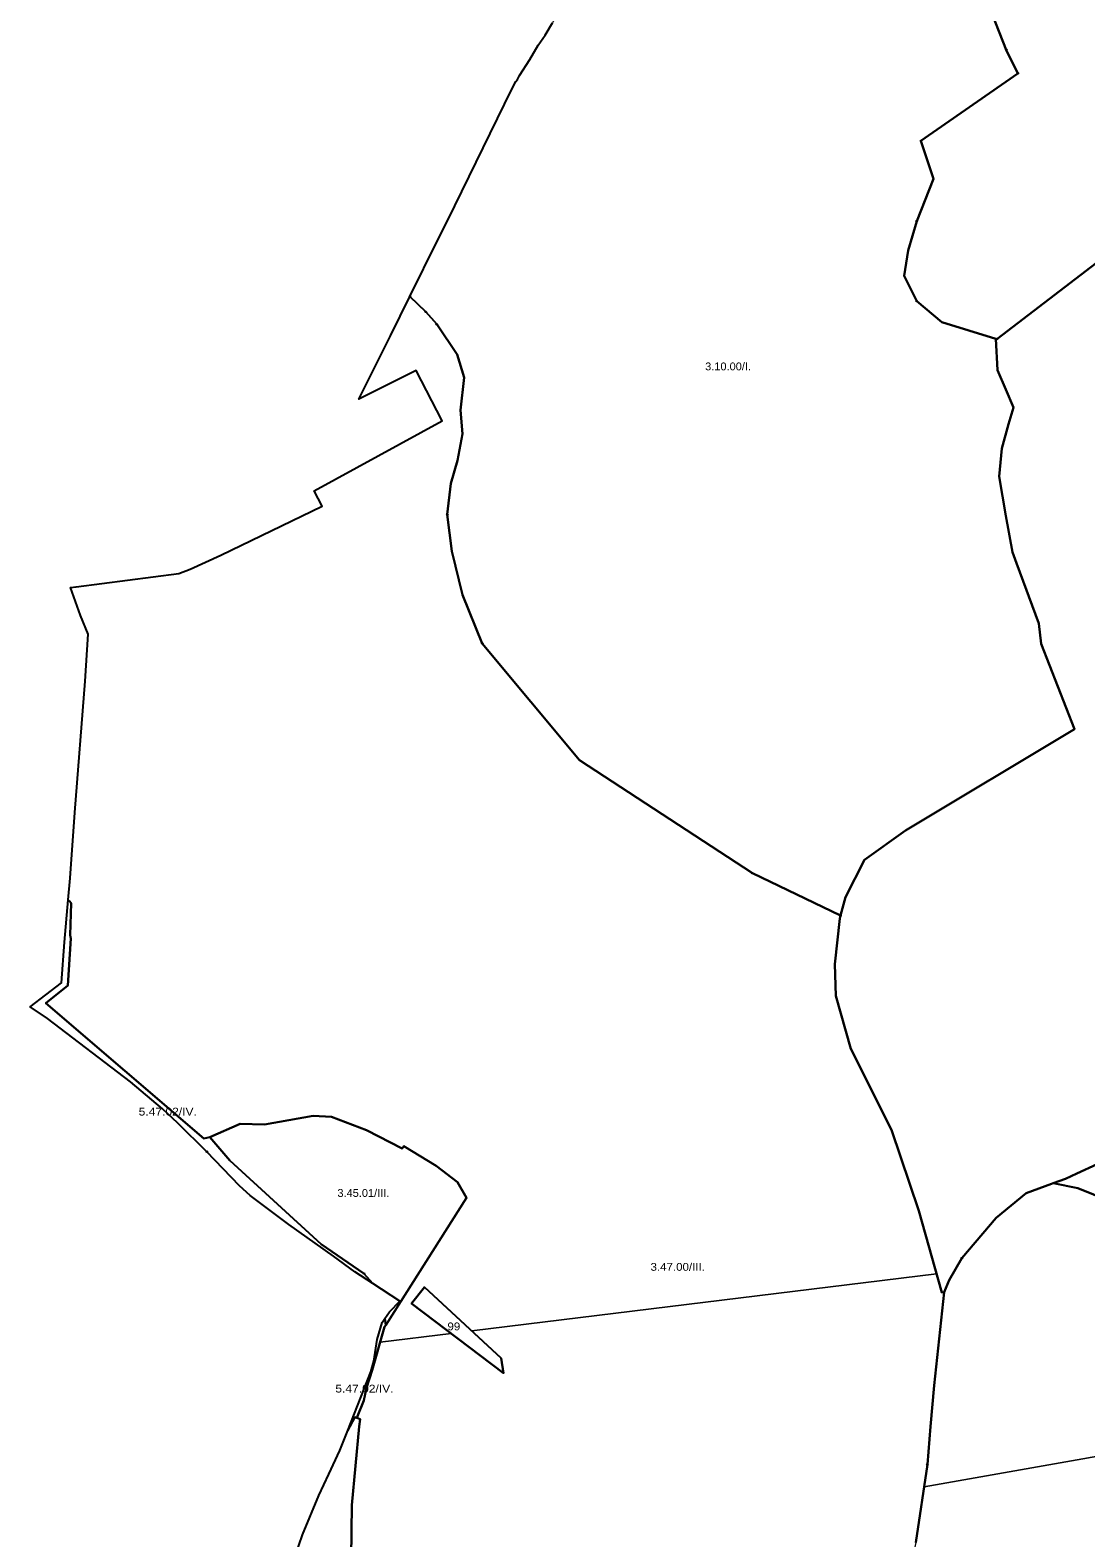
# Model space of a CAD drawing. Extents: x -650455 to -642254, y -1075222 to -1066610.
# Drawn here: x -649036 to -647687, y -1073142 to -1071216 of the extents above; entities that cross this region are included whole.
import ezdxf
from ezdxf.enums import TextEntityAlignment as Align

# ---------------------------------------------------------------- set-up
doc = ezdxf.new("R2010")
doc.units = 0
doc.header["$LTSCALE"] = 4
doc.header["$PDMODE"] = 32
doc.header["$PDSIZE"] = 2
for name, color, linetype, lineweight in [('1', 7, 'Continuous', 25), ('11', 7, 'Continuous', 13), ('12', 7, 'Continuous', 13), ('13', 7, 'Continuous', 13), ('14', 7, 'Continuous', 13)]:
    doc.layers.add(name, color=color, linetype=linetype, lineweight=lineweight)
doc.layers.add('2', color=7, linetype='Continuous')

msp = doc.modelspace()

# ---------------------------------------------------------------- linework, layer by layer
at = {"layer": '1'}
for points in [[(-647994, -1072324), (-648000.504, -1072347.414), (-648113.117, -1072293.193), (-648334.004, -1072148.767), (-648458.304, -1071999.711), (-648483.733, -1071937.503), (-648497.128, -1071881.651), (-648503.031, -1071835.108), (-648498.263, -1071795.376), (-648489.863, -1071765.861), (-648483.733, -1071731.805), (-648486, -1071701.501), (-648481.5, -1071660), (-648490.5, -1071630.501), (-648516.5, -1071592), (-648530.5, -1071576.001), (-648550.69, -1071556.284), (-648515.528, -1071484.719), (-648502.316, -1071458.869), (-648421.035, -1071292.285), (-648415.434, -1071281.946), (-648413.28, -1071279.36), (-648410.551, -1071274.192), (-648397.483, -1071253.511), (-648386.713, -1071235.418), (-648378.097, -1071222.492), (-648368.619, -1071206.983)], [(-647806.937, -1071195.687), (-647788.736, -1071241.189), (-647773.924, -1071271.486), (-647897.806, -1071357.665), (-647881.648, -1071406.14), (-647903.192, -1071460.002), (-647913.965, -1071497.705), (-647919.351, -1071530.022), (-647903.192, -1071562.339), (-647870.875, -1071589.27), (-647801.949, -1071610.478), (-647799.782, -1071650.366), (-647789.455, -1071675.321), (-647779.56, -1071698.124), (-647786.013, -1071719.637), (-647794.619, -1071750.616), (-647797.63, -1071786.328), (-647789.455, -1071836.453), (-647780.85, -1071882.921), (-647775.687, -1071897.12), (-647747.29, -1071974.351), (-647744.278, -1072000.167), (-647701.628, -1072109.378), (-647917.5, -1072238.5), (-647970, -1072276), (-647994, -1072324)], [(-647412.981, -1071489.088), (-647446.149, -1071408.082), (-647470.706, -1071328.032), (-647494.813, -1071270.777), (-647498.258, -1071279.39), (-647499.23, -1071276.872), (-647515.389, -1071314.575), (-647547.706, -1071336.12), (-647526.161, -1071400.754), (-647800.855, -1071610.814), (-647801.949, -1071610.478), (-647870.875, -1071589.27), (-647903.192, -1071562.339), (-647919.351, -1071530.022), (-647913.965, -1071497.705), (-647903.192, -1071460.002), (-647881.648, -1071406.14), (-647897.806, -1071357.665), (-647773.924, -1071271.486), (-647788.736, -1071241.189), (-647806.937, -1071195.687)], [(-647672.5, -1072665), (-647698.521, -1072676.851), (-647713.137, -1072683.505), (-647728.952, -1072689.256), (-647731, -1072690.001), (-647763.5, -1072702.001), (-647801.5, -1072733.5), (-647845.5, -1072785), (-647861.5, -1072813), (-647868, -1072828.501), (-647871, -1072829.001), (-647900.5, -1072724.5), (-647935.5, -1072621.001), (-647987.5, -1072517.5), (-648006.5, -1072450), (-648008, -1072409.5), (-648001.5, -1072351.001), (-648000.504, -1072347.414), (-647994, -1072324), (-647970, -1072276), (-647917.5, -1072238.5), (-647701.628, -1072109.378), (-647744.278, -1072000.167), (-647747.29, -1071974.351), (-647775.687, -1071897.12), (-647780.85, -1071882.921), (-647789.455, -1071836.453), (-647797.63, -1071786.328), (-647794.619, -1071750.616), (-647786.013, -1071719.637), (-647779.56, -1071698.124), (-647789.455, -1071675.321), (-647799.782, -1071650.366), (-647801.949, -1071610.478), (-647800.855, -1071610.814), (-647526.161, -1071400.754)], [(-648845.916, -1071910.237), (-648831.479, -1071904.954), (-648792.396, -1071886.988), (-648662.822, -1071824.472), (-648673.033, -1071804.745), (-648509.304, -1071715.273), (-648542.754, -1071651.164), (-648615.992, -1071687.445), (-648575.5, -1071606.779), (-648550.69, -1071556.284), (-648530.5, -1071576.001), (-648516.5, -1071592), (-648490.5, -1071630.501)], [(-648490.5, -1071630.501), (-648481.5, -1071660), (-648486, -1071701.501), (-648483.733, -1071731.805), (-648489.863, -1071765.861), (-648498.263, -1071795.376), (-648503.031, -1071835.108), (-648497.128, -1071881.651), (-648483.733, -1071937.503), (-648458.304, -1071999.711), (-648334.004, -1072148.767), (-648113.117, -1072293.193), (-648000.504, -1072347.414), (-648001.5, -1072351.001), (-648008, -1072409.5), (-648006.5, -1072450), (-647987.5, -1072517.5), (-647935.5, -1072621.001), (-647900.5, -1072724.5), (-647871, -1072829.001), (-647868, -1072828.501), (-647881, -1072947.5), (-647885.418, -1073000), (-647889.5, -1073048.5), (-647904.5, -1073148.001)], [(-648626.5, -1073235.5), (-648625, -1073100.5), (-648615.407, -1073000), (-648614.5, -1072990.501), (-648618.5, -1072989), (-648609.5, -1072967), (-648606, -1072950.5), (-648599, -1072928), (-648583, -1072872.501), (-648581.642, -1072870.363), (-648478.5, -1072708), (-648490, -1072688), (-648517, -1072667.001), (-648558.691, -1072641.986), (-648560.5, -1072645.001), (-648606, -1072621.501), (-648651, -1072604.501), (-648674.5, -1072603), (-648736.5, -1072614.001), (-648767.5, -1072613.501), (-648806.5, -1072630.501), (-648814, -1072632), (-649016, -1072459.001), (-648988, -1072436.5), (-648984, -1072376.5), (-648985, -1072372.5), (-648983.5, -1072331.5), (-648985.611, -1072329.098), (-648987.292, -1072327.185), (-648984.907, -1072299.389), (-648978.921, -1072215.554), (-648965.541, -1072047.881), (-648961.667, -1071987.999), (-648971.526, -1071964.046), (-648984.389, -1071928.3), (-648977.161, -1071927.325), (-648845.916, -1071910.237)], [(-647639.5, -1072719.001), (-647697.5, -1072695.5), (-647728.952, -1072689.256), (-647713.137, -1072683.505), (-647698.521, -1072676.851), (-647672.5, -1072665), (-647660, -1072659.5), (-647610, -1072633.501), (-647571.5, -1072606.001), (-647536, -1072573.001), (-647511.5, -1072543), (-647500, -1072504.667), (-647498, -1072498), (-647495, -1072475.501), (-647474.5, -1072442.501), (-647439.5, -1072402.001), (-647391, -1072357), (-647361, -1072335.5), (-647349, -1072333), (-647336.5, -1072335.5), (-647316, -1072351.5), (-647308, -1072361.501)], [(-647904.5, -1073148.001), (-647889.5, -1073048.5), (-647885.418, -1073000), (-647881, -1072947.5), (-647868, -1072828.501), (-647861.5, -1072813), (-647845.5, -1072785), (-647801.5, -1072733.5), (-647763.5, -1072702.001), (-647731, -1072690.001), (-647728.952, -1072689.256), (-647697.5, -1072695.5), (-647639.5, -1072719.001), (-647587, -1072756.001), (-647543, -1072805.5), (-647522, -1072821.5), (-647515.5, -1072825), (-647500, -1072834.548), (-647453, -1072863.5), (-647421.34, -1072872.531), (-647410, -1072877.001), (-647339.5, -1072889.001)], [(-648697.333, -1073165.774), (-648687.999, -1073138.202), (-648667.032, -1073088.227), (-648654.486, -1073060.948), (-648640.322, -1073030.783), (-648630.2, -1073005.113), (-648627.452, -1073000), (-648621, -1072988), (-648618.5, -1072989), (-648614.5, -1072990.501), (-648615.407, -1073000), (-648625, -1073100.5), (-648626.5, -1073235.5)]]:
    msp.add_lwpolyline(points, dxfattribs=at)
for points in [[(-649016, -1072459.001), (-648814, -1072632), (-648806.5, -1072630.501), (-648781, -1072660), (-648664, -1072767.001), (-648609.5, -1072804.501), (-648598.112, -1072817.407), (-648620.935, -1072802.594), (-648648.364, -1072782.202), (-648705.519, -1072741.992), (-648754.776, -1072704.94), (-648768.275, -1072692.734), (-648810.208, -1072648.934), (-648847.402, -1072612.314), (-648866.789, -1072594.363), (-648907.86, -1072559.755), (-649013.849, -1072478.813), (-649035.963, -1072463.892), (-648995.823, -1072433.245), (-648991.95, -1072381.465), (-648987.292, -1072327.185), (-648985.611, -1072329.098), (-648983.5, -1072331.5), (-648985, -1072372.5), (-648984, -1072376.5), (-648988, -1072436.5)], [(-648581.642, -1072870.363), (-648582.835, -1072862.192), (-648576.781, -1072853.444), (-648563.753, -1072839.708), (-648598.112, -1072817.407), (-648609.5, -1072804.501), (-648664, -1072767.001), (-648781, -1072660), (-648806.5, -1072630.501), (-648767.5, -1072613.501), (-648736.5, -1072614.001), (-648674.5, -1072603), (-648651, -1072604.501), (-648606, -1072621.501), (-648560.5, -1072645.001), (-648558.691, -1072641.986), (-648517, -1072667.001), (-648490, -1072688), (-648478.5, -1072708)], [(-648434, -1072912.501), (-648431, -1072932), (-648548.5, -1072843), (-648532, -1072822)], [(-648548.5, -1072843), (-648431, -1072932), (-648434, -1072912.501), (-648532, -1072822)], [(-648609.5, -1072967), (-648618.5, -1072989), (-648621, -1072988), (-648627.452, -1073000), (-648630.2, -1073005.113), (-648600.686, -1072930.26), (-648596.665, -1072916.474), (-648592.501, -1072888.9), (-648586.288, -1072867.182), (-648582.835, -1072862.192), (-648581.642, -1072870.363), (-648583, -1072872.501), (-648599, -1072928), (-648606, -1072950.5)]]:
    msp.add_lwpolyline(points, close=True, dxfattribs=at)
at = {"layer": '11'}
msp.add_line((-647788.736, -1071241.189), (-647806.937, -1071195.687), dxfattribs=at)
for points in [[(-648327.713, -1071139.525), (-648367.47, -1071204.399), (-648368.619, -1071206.983), (-648378.097, -1071222.492), (-648386.713, -1071235.418), (-648397.483, -1071253.511), (-648410.551, -1071274.192), (-648413.28, -1071279.36), (-648415.434, -1071281.946), (-648421.035, -1071292.285), (-648502.316, -1071458.869), (-648515.528, -1071484.719), (-648550.69, -1071556.284)], [(-647897.806, -1071357.665), (-647773.924, -1071271.486), (-647788.736, -1071241.189)], [(-647903.192, -1071460.002), (-647881.648, -1071406.14), (-647897.806, -1071357.665)], [(-647526.161, -1071400.754), (-647800.855, -1071610.814), (-647801.949, -1071610.478), (-647799.782, -1071650.366), (-647789.455, -1071675.321), (-647779.56, -1071698.124), (-647786.013, -1071719.637), (-647794.619, -1071750.616), (-647797.63, -1071786.328), (-647789.455, -1071836.453), (-647780.85, -1071882.921), (-647775.687, -1071897.12), (-647747.29, -1071974.351), (-647744.278, -1072000.167), (-647701.628, -1072109.378), (-647917.5, -1072238.5), (-647970, -1072276), (-647994, -1072324), (-648000.504, -1072347.414)], [(-647903.192, -1071562.339), (-647919.351, -1071530.022), (-647913.965, -1071497.705), (-647903.192, -1071460.002)], [(-648550.69, -1071556.284), (-648530.5, -1071576.001), (-648516.5, -1071592)], [(-648334.004, -1072148.767), (-648113.117, -1072293.193), (-648000.504, -1072347.414), (-647994, -1072324), (-647970, -1072276), (-647917.5, -1072238.5), (-647701.628, -1072109.378), (-647744.278, -1072000.167), (-647747.29, -1071974.351), (-647775.687, -1071897.12), (-647780.85, -1071882.921), (-647789.455, -1071836.453), (-647797.63, -1071786.328), (-647794.619, -1071750.616), (-647786.013, -1071719.637), (-647779.56, -1071698.124), (-647789.455, -1071675.321), (-647799.782, -1071650.366), (-647801.949, -1071610.478), (-647870.875, -1071589.27), (-647903.192, -1071562.339)], [(-648516.5, -1071592), (-648490.5, -1071630.501), (-648481.5, -1071660), (-648486, -1071701.501), (-648483.733, -1071731.805), (-648489.863, -1071765.861), (-648498.263, -1071795.376), (-648503.031, -1071835.108)], [(-648503.031, -1071835.108), (-648497.128, -1071881.651), (-648483.733, -1071937.503), (-648458.304, -1071999.711), (-648334.004, -1072148.767)], [(-648000.504, -1072347.414), (-648001.5, -1072351.001), (-648008, -1072409.5), (-648006.5, -1072450), (-647987.5, -1072517.5), (-647935.5, -1072621.001), (-647900.5, -1072724.5), (-647871, -1072829.001), (-647868, -1072828.501), (-647861.5, -1072813), (-647845.5, -1072785)], [(-647845.5, -1072785), (-647801.5, -1072733.5), (-647763.5, -1072702.001), (-647731, -1072690.001), (-647728.952, -1072689.256), (-647713.137, -1072683.505), (-647698.521, -1072676.851), (-647672.5, -1072665), (-647660, -1072659.5), (-647610, -1072633.501), (-647571.5, -1072606.001), (-647536, -1072573.001), (-647511.5, -1072543), (-647500, -1072504.667), (-647498, -1072498), (-647495, -1072475.501), (-647474.5, -1072442.501), (-647439.5, -1072402.001), (-647391, -1072357), (-647361, -1072335.5), (-647349, -1072333), (-647336.5, -1072335.5), (-647316, -1072351.5), (-647308, -1072361.501)], [(-647421.34, -1072872.531), (-647453, -1072863.5), (-647500, -1072834.548), (-647515.5, -1072825), (-647522, -1072821.5), (-647543, -1072805.5), (-647587, -1072756.001), (-647639.5, -1072719.001), (-647697.5, -1072695.5), (-647728.952, -1072689.256), (-647731, -1072690.001), (-647763.5, -1072702.001), (-647801.5, -1072733.5), (-647845.5, -1072785), (-647861.5, -1072813), (-647868, -1072828.501), (-647881, -1072947.5), (-647885.418, -1073000), (-647889.5, -1073048.5)], [(-647339.5, -1072889.001), (-647407.174, -1072877.482), (-647467.805, -1073000), (-647452.469, -1073000), (-647459.21, -1073004.071), (-647476.435, -1073003.416), (-647893.795, -1073076.991), (-647904.5, -1073148.001), (-647917.5, -1073209.501), (-647919.5, -1073256), (-647914.5, -1073287.5), (-647902, -1073313.501), (-647885, -1073332.5), (-647865, -1073347.001), (-647852.5, -1073352.5), (-647735.5, -1073384), (-647648, -1073415.501), (-647589.5, -1073433)], [(-647889.5, -1073048.5), (-647893.795, -1073076.991), (-647476.435, -1073003.416)]]:
    msp.add_lwpolyline(points, dxfattribs=at)
for p in [(-647788.736, -1071241.189), (-647897.806, -1071357.665), (-647903.192, -1071460.002), (-648550.69, -1071556.284), (-647903.192, -1071562.339), (-648516.5, -1071592), (-648503.031, -1071835.108), (-648000.504, -1072347.414), (-647845.5, -1072785), (-647889.5, -1073048.5)]:
    msp.add_point(p, dxfattribs=at)
at = {"layer": '12'}
for points in [[(-648110.225, -1071019.369), (-647998.802, -1070960.38), (-647920.15, -1070914.5), (-647887.378, -1070888.282), (-647867.716, -1070875.174), (-647858.53, -1070886.459), (-647842.598, -1070939.564), (-647837.212, -1071004.198), (-647821.053, -1071058.06), (-647804.895, -1071111.921), (-647810.281, -1071160.397), (-647810.281, -1071187.327), (-647806.937, -1071195.687), (-647788.736, -1071241.189), (-647773.924, -1071271.486)], [(-647773.924, -1071271.486), (-647897.806, -1071357.665), (-647881.648, -1071406.14), (-647903.192, -1071460.002), (-647913.965, -1071497.705), (-647919.351, -1071530.022), (-647903.192, -1071562.339), (-647870.875, -1071589.27), (-647801.949, -1071610.478), (-647800.855, -1071610.814)], [(-647800.855, -1071610.814), (-647526.161, -1071400.754), (-647547.706, -1071336.12)]]:
    msp.add_lwpolyline(points, dxfattribs=at)
for p in [(-647773.924, -1071271.486), (-647800.855, -1071610.814)]:
    msp.add_point(p, dxfattribs=at)
at = {"layer": '13'}
msp.add_line((-648000.504, -1072347.414), (-648113.117, -1072293.193), dxfattribs=at)
for points in [[(-648530.5, -1071576.001), (-648550.69, -1071556.284), (-648575.5, -1071606.779), (-648615.992, -1071687.445), (-648542.754, -1071651.164), (-648509.304, -1071715.273), (-648673.033, -1071804.745), (-648662.822, -1071824.472), (-648792.396, -1071886.988), (-648831.479, -1071904.954), (-648845.916, -1071910.237), (-648977.161, -1071927.325), (-648984.389, -1071928.3), (-648971.526, -1071964.046), (-648961.667, -1071987.999), (-648965.541, -1072047.881), (-648978.921, -1072215.554), (-648984.907, -1072299.389), (-648987.292, -1072327.185), (-648985.611, -1072329.098), (-648983.5, -1072331.5), (-648985, -1072372.5), (-648984, -1072376.5), (-648988, -1072436.5), (-649016, -1072459.001), (-648814, -1072632), (-648806.5, -1072630.501), (-648767.5, -1072613.501), (-648736.5, -1072614.001), (-648674.5, -1072603), (-648651, -1072604.501), (-648606, -1072621.501), (-648560.5, -1072645.001), (-648558.691, -1072641.986), (-648517, -1072667.001), (-648490, -1072688), (-648478.5, -1072708), (-648581.642, -1072870.363), (-648583, -1072872.501), (-648588.72, -1072892.343)], [(-648458.304, -1071999.711), (-648483.733, -1071937.503), (-648497.128, -1071881.651), (-648503.031, -1071835.108), (-648498.263, -1071795.376), (-648489.863, -1071765.861), (-648483.733, -1071731.805), (-648486, -1071701.501), (-648481.5, -1071660), (-648490.5, -1071630.501), (-648516.5, -1071592), (-648530.5, -1071576.001)], [(-648113.117, -1072293.193), (-648334.004, -1072148.767), (-648458.304, -1071999.711)], [(-648471.444, -1072877.922), (-647877.798, -1072804.921), (-647900.5, -1072724.5), (-647935.5, -1072621.001), (-647987.5, -1072517.5), (-648006.5, -1072450), (-648008, -1072409.5), (-648001.5, -1072351.001), (-648000.504, -1072347.414)], [(-647308, -1072361.501), (-647316, -1072351.5), (-647336.5, -1072335.5), (-647349, -1072333), (-647361, -1072335.5), (-647391, -1072357), (-647439.5, -1072402.001), (-647474.5, -1072442.501), (-647495, -1072475.501), (-647498, -1072498), (-647500, -1072504.667), (-647511.5, -1072543), (-647536, -1072573.001), (-647571.5, -1072606.001), (-647610, -1072633.501), (-647660, -1072659.5), (-647672.5, -1072665), (-647698.521, -1072676.851), (-647713.137, -1072683.505), (-647728.952, -1072689.256), (-647697.5, -1072695.5), (-647639.5, -1072719.001), (-647587, -1072756.001)], [(-647904.5, -1073148.001), (-647893.795, -1073076.991), (-647889.5, -1073048.5), (-647885.418, -1073000), (-647881, -1072947.5), (-647868, -1072828.501), (-647871, -1072829.001), (-647877.798, -1072804.921), (-648471.444, -1072877.922), (-648434, -1072912.501), (-648431, -1072932), (-648498.072, -1072881.196), (-648588.72, -1072892.343), (-648599, -1072928), (-648606, -1072950.5), (-648609.5, -1072967), (-648618.5, -1072989), (-648614.5, -1072990.501), (-648615.407, -1073000), (-648625, -1073100.5), (-648626.5, -1073235.5)], [(-648588.72, -1072892.343), (-648498.072, -1072881.196), (-648548.5, -1072843), (-648532, -1072822), (-648471.444, -1072877.922)], [(-648626.5, -1073235.5), (-648625, -1073100.5), (-648615.407, -1073000), (-648614.5, -1072990.501), (-648618.5, -1072989), (-648621, -1072988), (-648627.452, -1073000), (-648630.2, -1073005.113), (-648640.322, -1073030.783), (-648654.486, -1073060.948), (-648667.032, -1073088.227), (-648687.999, -1073138.202), (-648697.333, -1073165.774)]]:
    msp.add_lwpolyline(points, dxfattribs=at)
msp.add_lwpolyline([(-648609.5, -1072804.501), (-648598.112, -1072817.407), (-648563.753, -1072839.708), (-648576.781, -1072853.444), (-648582.835, -1072862.192), (-648581.642, -1072870.363), (-648478.5, -1072708), (-648490, -1072688), (-648517, -1072667.001), (-648558.691, -1072641.986), (-648560.5, -1072645.001), (-648606, -1072621.501), (-648651, -1072604.501), (-648674.5, -1072603), (-648736.5, -1072614.001), (-648767.5, -1072613.501), (-648806.5, -1072630.501), (-648781, -1072660), (-648664, -1072767.001)], close=True, dxfattribs=at)
for p in [(-648530.5, -1071576.001), (-648458.304, -1071999.711), (-648113.117, -1072293.193), (-648000.504, -1072347.414), (-648609.5, -1072804.501)]:
    msp.add_point(p, dxfattribs=at)
at = {"layer": '14'}
for points in [[(-648810.208, -1072648.934), (-648768.275, -1072692.734), (-648754.776, -1072704.94), (-648705.519, -1072741.992), (-648648.364, -1072782.202), (-648620.935, -1072802.594), (-648598.112, -1072817.407), (-648609.5, -1072804.501), (-648664, -1072767.001), (-648781, -1072660), (-648806.5, -1072630.501), (-648814, -1072632), (-649016, -1072459.001), (-648988, -1072436.5), (-648984, -1072376.5), (-648985, -1072372.5), (-648983.5, -1072331.5), (-648985.611, -1072329.098), (-648987.292, -1072327.185), (-648991.95, -1072381.465), (-648995.823, -1072433.245), (-649035.963, -1072463.892), (-649013.849, -1072478.813), (-648907.86, -1072559.755), (-648866.789, -1072594.363), (-648847.402, -1072612.314)], [(-648630.2, -1073005.113), (-648627.452, -1073000), (-648621, -1072988), (-648618.5, -1072989), (-648609.5, -1072967), (-648606, -1072950.5), (-648599, -1072928), (-648598.992, -1072927.973), (-648588.72, -1072892.343), (-648583, -1072872.501), (-648581.642, -1072870.363), (-648582.835, -1072862.192), (-648586.288, -1072867.182), (-648592.501, -1072888.9), (-648596.665, -1072916.474), (-648600.686, -1072930.26)]]:
    msp.add_lwpolyline(points, close=True, dxfattribs=at)
msp.add_point((-648810.208, -1072648.934), dxfattribs=at)

# ---------------------------------------------------------------- texts
at = {"layer": '2'}
for s, width, p in [('3.10.00/I.', 1.05, (-648144.21, -1071650.733)), ('5.47.02/IV.', 1.15, (-648860.112, -1072602.781)), ('3.45.01/III.', 1.05, (-648610.155, -1072706.687)), ('3.47.00/III.', 1.1, (-648208.521, -1072801.06)), ('99', 1.1, (-648494.584, -1072877.117)), ('5.47.02/IV.', 1.15, (-648608.822, -1072956.603))]:
    msp.add_text(s, height=10, dxfattribs=dict(at, width=width)).set_placement(p, align=Align.CENTER)

doc.saveas('drawing.dxf')
